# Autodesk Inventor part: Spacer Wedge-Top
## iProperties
Created: 2006-12
Part Number: Spacer Wedge-Top
Document SubType Name: Modeling
Designer: Administrator
Density: 1 g/cm^3
Author: Administrator
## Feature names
1. Extrusion1
2. Extrusion3
3. Extrusion4
4. Extrusion5
5. Extrusion6
